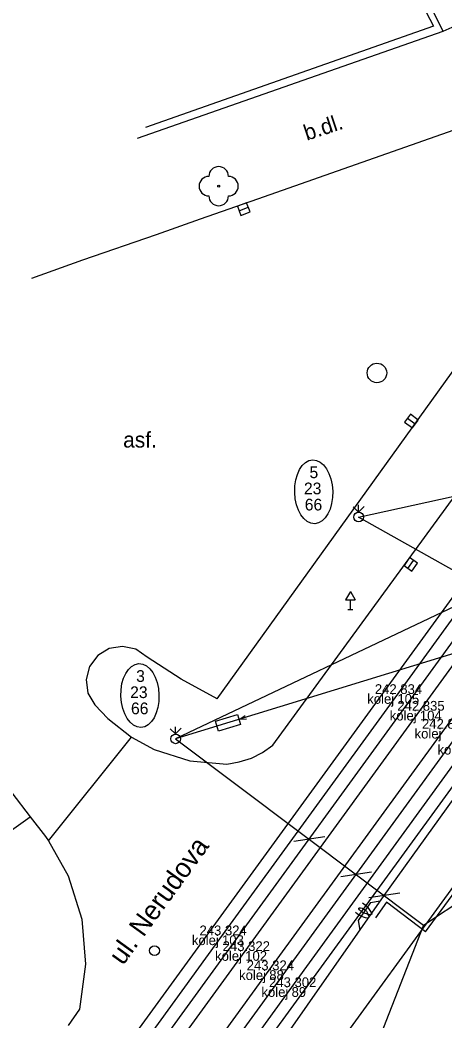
# Model space of a CAD drawing. Extents: x -599098 to -598820, y -1159597 to -1158744.
# Drawn here: x -598947.5 to -598925.7, y -1159416.5 to -1159365.4 of the extents above; entities that cross this region are included whole.
import ezdxf

# ---------------------------------------------------------------- set-up
doc = ezdxf.new("R2010")
doc.units = 0
for name, color, linetype in [('body', 7, 'Continuous'), ('druh pozemku stromy', 7, 'Continuous'), ('kresba', 7, 'Continuous'), ('kódy bodů', 7, 'Continuous'), ('popisy', 7, 'Continuous'), ('tram_koleje', 7, 'Continuous'), ('tram_osa', 7, 'Continuous'), ('trol_detaily', 7, 'Continuous'), ('trol_převěsy', 7, 'Continuous'), ('trol_troljová stopa', 7, 'Continuous'), ('trol_ved sloupy konzoly', 7, 'Continuous'), ('trol_čísla sloupů', 7, 'Continuous'), ('výšky bodů', 7, 'Continuous'), ('značky IS', 7, 'Continuous'), ('čísla bodů', 7, 'Continuous')]:
    doc.layers.add(name, color=color, linetype=linetype)

msp = doc.modelspace()

# ---------------------------------------------------------------- linework, layer by layer
at = {"layer": 'body'}
for p, q in [((-598928.176, -1159399.837), (-598928.176, -1159399.837)), ((-598927.027, -1159400.69), (-598927.027, -1159400.69)), ((-598925.758, -1159401.611), (-598925.758, -1159401.611)), ((-598937.138, -1159412.175), (-598937.138, -1159412.175)), ((-598935.954, -1159412.979), (-598935.954, -1159412.979)), ((-598934.725, -1159413.961), (-598934.725, -1159413.961)), ((-598933.584, -1159414.824), (-598933.584, -1159414.824))]:
    msp.add_line(p, q, dxfattribs=at)
at = {"layer": 'druh pozemku stromy'}
msp.add_circle((-598937.31, -1159373.87), 0.05, dxfattribs=at)
for centre, start, end in [((-598937.31, -1159373.37), 0, 180), ((-598937.81, -1159373.87), 90, 270), ((-598936.81, -1159373.87), 270, 90), ((-598937.31, -1159374.37), 180, 0)]:
    msp.add_arc(centre, 0.5, start, end, dxfattribs=at)
at = {"layer": 'kresba'}
for p, q in [((-598929.98, -1159358.68), (-598926.33, -1159365.69)), ((-598925.84, -1159365.94), (-598929.62, -1159358.47)), ((-598941.464, -1159371.415), (-598925.84, -1159365.94)), ((-598926.33, -1159365.69), (-598941.055, -1159370.872)), ((-598925.84, -1159365.94), (-598925.23, -1159365.67)), ((-598934.54, -1159402.45), (-598916.76, -1159378.057)), ((-598915.031, -1159380.678), (-598951.27, -1159430.52)), ((-598954.76, -1159445), (-598910.397, -1159384.001)), ((-598946, -1159407.35), (-598941.77, -1159402.04)), ((-598949.59, -1159407.99), (-598946.94, -1159406.11)), ((-598944.42, -1159415.95), (-598945.01, -1159416.79))]:
    msp.add_line(p, q, dxfattribs=at)
for points in [[(-598918.73, -1159368.69), (-598921.45, -1159369.65), (-598924.03, -1159370.56), (-598935.33, -1159374.54), (-598938.26, -1159375.56), (-598940.5, -1159376.36), (-598944.27, -1159377.65), (-598946.87, -1159378.584)], [(-598937.39, -1159400.08), (-598916.76, -1159371.39), (-598918.73, -1159368.69)], [(-598971.318, -1159473.04), (-598937.35, -1159426.23), (-598935.58, -1159423.81), (-598907.272, -1159384.872)], [(-598940.97, -1159397.95), (-598941.54, -1159397.55), (-598942.22, -1159397.4), (-598942.9, -1159397.51), (-598943.49, -1159397.87), (-598943.91, -1159398.43), (-598944.08, -1159399.1), (-598943.99, -1159399.79), (-598943.64, -1159400.39)], [(-598937.39, -1159400.08), (-598939.22, -1159399.08), (-598940.97, -1159397.95)], [(-598952.58, -1159398.75), (-598946.94, -1159406.11), (-598946.16, -1159407.13)], [(-598943.64, -1159400.39), (-598942.98, -1159401.09), (-598941.77, -1159402.04), (-598940.61, -1159402.68), (-598938.79, -1159403.26), (-598936.89, -1159403.42), (-598936.26, -1159403.31), (-598935.64, -1159403.11), (-598935.07, -1159402.82), (-598934.54, -1159402.45)], [(-598946.16, -1159407.13), (-598946, -1159407.35), (-598945, -1159409.14), (-598944.31, -1159411.35), (-598944.11, -1159413.65), (-598944.42, -1159415.95)]]:
    msp.add_lwpolyline(points, dxfattribs=at)
at = {"layer": 'tram_koleje'}
for p, q in [((-598923.855, -1159393.884), (-598928.176, -1159399.837)), ((-598927.027, -1159400.69), (-598922.702, -1159394.734)), ((-598925.758, -1159401.611), (-598921.447, -1159395.676)), ((-598928.176, -1159399.837), (-598937.138, -1159412.175)), ((-598935.954, -1159412.979), (-598927.027, -1159400.69)), ((-598934.725, -1159413.961), (-598925.758, -1159401.611)), ((-598924.585, -1159402.432), (-598933.584, -1159414.824)), ((-598937.138, -1159412.175), (-598946.113, -1159424.535)), ((-598944.977, -1159425.405), (-598935.954, -1159412.979)), ((-598943.721, -1159426.356), (-598934.725, -1159413.961)), ((-598933.584, -1159414.824), (-598942.59, -1159427.231))]:
    msp.add_line(p, q, dxfattribs=at)
at = {"layer": 'tram_osa'}
for points in [[(-598977.263, -1159468.664), (-598954.574, -1159437.402), (-598945.545, -1159424.97), (-598936.546, -1159412.577), (-598927.601, -1159400.263), (-598923.278, -1159394.309), (-598920.261, -1159390.154), (-598913.36, -1159380.656), (-598912.708, -1159379.754), (-598911.697, -1159378.368), (-598910.561, -1159376.808)], [(-598974.831, -1159470.439), (-598952.096, -1159439.109), (-598943.155, -1159426.793), (-598934.154, -1159414.392), (-598925.171, -1159402.021), (-598920.866, -1159396.094), (-598917.823, -1159391.902), (-598910.877, -1159382.349), (-598910.288, -1159381.538), (-598908.157, -1159378.609)]]:
    msp.add_lwpolyline(points, dxfattribs=at)
at = {"layer": 'trol_detaily'}
for p, q in [((-598926.74, -1159411.99), (-598916.72, -1159398.35)), ((-598936.269, -1159401.133), (-598935.952, -1159400.934)), ((-598935.894, -1159401.12), (-598936.269, -1159401.133)), ((-598931.892, -1159407.143), (-598933.474, -1159407.376)), ((-598929.493, -1159408.946), (-598931.075, -1159409.179)), ((-598929.55, -1159410.495), (-598930.189, -1159411.413)), ((-598928.058, -1159410.023), (-598929.64, -1159410.256)), ((-598929.55, -1159410.495), (-598929.058, -1159410.407)), ((-598928.74, -1159410.48), (-598929.3, -1159411.28)), ((-598926.74, -1159411.99), (-598928.74, -1159410.48)), ((-598930.189, -1159411.413), (-598930.099, -1159411.907))]:
    msp.add_line(p, q, dxfattribs=at)
msp.add_lwpolyline([(-598937.472, -1159401.223), (-598936.348, -1159400.877), (-598936.19, -1159401.39), (-598937.314, -1159401.736)], close=True, dxfattribs=at)
msp.add_open_spline([(-598929.961, -1159410.506), (-598929.851, -1159410.576), (-598929.705, -1159410.705), (-598929.358, -1159411.207), (-598929.808, -1159411.069), (-598929.977, -1159411.001), (-598930.259, -1159410.722), (-598929.868, -1159410.81), (-598929.733, -1159410.97), (-598929.537, -1159411.39), (-598930.045, -1159411.205), (-598930.206, -1159411.113), (-598930.311, -1159411.017)], degree=3, dxfattribs=at)
at = {"layer": 'trol_převěsy'}
for p, q in [((-598903.14, -1159384.83), (-598939.51, -1159402.13)), ((-598930.16, -1159390.79), (-598903.14, -1159384.83)), ((-598913.68, -1159400.06), (-598930.16, -1159390.79)), ((-598921.554, -1159396.606), (-598939.51, -1159402.13)), ((-598939.51, -1159402.13), (-598926.84, -1159411.65)), ((-598926.84, -1159411.65), (-598917.69, -1159405.57)), ((-598926.84, -1159411.65), (-598932.51, -1159426.11))]:
    msp.add_line(p, q, dxfattribs=at)
at = {"layer": 'trol_troljová stopa'}
for p, q in [((-598928.85, -1159410.14), (-598919.33, -1159396.88)), ((-598937.74, -1159422.84), (-598928.85, -1159410.14))]:
    msp.add_line(p, q, dxfattribs=at)
at = {"layer": 'trol_ved sloupy konzoly'}
for p, q in [((-598930.164, -1159390.541), (-598930.439, -1159390.274)), ((-598930.164, -1159390.541), (-598930.17, -1159390.169)), ((-598930.164, -1159390.541), (-598929.878, -1159390.248)), ((-598939.514, -1159401.881), (-598939.789, -1159401.614)), ((-598939.514, -1159401.881), (-598939.52, -1159401.509)), ((-598939.514, -1159401.881), (-598939.228, -1159401.588))]:
    msp.add_line(p, q, dxfattribs=at)
for centre in [(-598930.16, -1159390.79), (-598939.51, -1159402.13)]:
    msp.add_circle(centre, 0.248, dxfattribs=at)
at = {"layer": 'trol_čísla sloupů'}
for centre in [(-598932.453, -1159389.495), (-598941.335, -1159399.914)]:
    msp.add_ellipse(centre, major_axis=(0.051, -1.632), ratio=0.595913, dxfattribs=at)
at = {"layer": 'značky IS'}
for p, q in [((-598936.263, -1159375.131), (-598935.797, -1159374.951)), ((-598927.661, -1159385.73), (-598927.262, -1159386.03)), ((-598927.635, -1159393.413), (-598927.345, -1159393.006)), ((-598930.58, -1159394.587), (-598930.83, -1159395.02)), ((-598930.58, -1159394.587), (-598930.83, -1159395.02)), ((-598930.58, -1159394.587), (-598930.33, -1159395.02)), ((-598930.58, -1159394.587), (-598930.33, -1159395.02)), ((-598930.83, -1159395.02), (-598930.33, -1159395.02)), ((-598930.83, -1159395.02), (-598930.33, -1159395.02)), ((-598930.58, -1159395.52), (-598930.58, -1159395.02)), ((-598930.58, -1159395.52), (-598930.58, -1159395.02)), ((-598930.705, -1159395.52), (-598930.455, -1159395.52)), ((-598930.705, -1159395.52), (-598930.455, -1159395.52))]:
    msp.add_line(p, q, dxfattribs=at)
for points in [[(-598936.173, -1159375.364), (-598935.707, -1159375.184), (-598935.887, -1159374.717), (-598936.354, -1159374.898)], [(-598927.811, -1159385.93), (-598927.411, -1159386.23), (-598927.111, -1159385.83), (-598927.512, -1159385.53)], [(-598927.431, -1159393.558), (-598927.141, -1159393.15), (-598927.549, -1159392.861), (-598927.838, -1159393.269)]]:
    msp.add_lwpolyline(points, close=True, dxfattribs=at)
for centre, radius in [((-598929.22, -1159383.42), 0.5), ((-598940.59, -1159412.96), 0.25)]:
    msp.add_circle(centre, radius, dxfattribs=at)

# ---------------------------------------------------------------- texts
at = {"layer": 'kódy bodů'}
for p in [(-598929.716, -1159400.337), (-598928.567, -1159401.19), (-598927.298, -1159402.111), (-598926.125, -1159402.932), (-598938.678, -1159412.675), (-598937.494, -1159413.479), (-598936.265, -1159414.461), (-598935.124, -1159415.324)]:
    msp.add_text('kolej', height=0.5, dxfattribs=at).set_placement(p)
at = {"layer": 'popisy'}
for s, height, rotation, p in [('b.dl.', 0.8, 18.2384, (-598932.807, -1159371.551)), ('ul. Nerudova', 1, 54.1243, (-598942.201, -1159413.755))]:
    msp.add_text(s, height=height, rotation=rotation, dxfattribs=at).set_placement(p)
msp.add_text('asf.', height=0.8, dxfattribs=at).set_placement((-598942.193, -1159387.235))
at = {"layer": 'trol_čísla sloupů'}
for s, p in [('5', (-598932.668, -1159388.799)), ('23', (-598932.953, -1159389.625)), ('66', (-598932.91, -1159390.452)), ('3', (-598941.528, -1159399.218)), ('23', (-598941.835, -1159400.045)), ('66', (-598941.792, -1159400.872))]:
    msp.add_text(s, height=0.6, dxfattribs=at).set_placement(p)
at = {"layer": 'výšky bodů'}
for s, p in [('242.834', (-598929.328, -1159399.837)), ('242.835', (-598928.179, -1159400.69)), ('242.836', (-598926.918, -1159401.611)), ('243.324', (-598938.29, -1159412.175)), ('243.322', (-598937.106, -1159412.979)), ('243.324', (-598935.877, -1159413.961)), ('243.302', (-598934.736, -1159414.824))]:
    msp.add_text(s, height=0.5, dxfattribs=at).set_placement(p)
at = {"layer": 'čísla bodů'}
for s, p in [('105', (-598928.176, -1159400.337)), ('104', (-598927.027, -1159401.19)), ('103', (-598937.138, -1159412.675)), ('102', (-598935.954, -1159413.479)), ('88', (-598934.725, -1159414.461)), ('89', (-598933.584, -1159415.324))]:
    msp.add_text(s, height=0.5, dxfattribs=at).set_placement(p)

doc.saveas('drawing.dxf')
